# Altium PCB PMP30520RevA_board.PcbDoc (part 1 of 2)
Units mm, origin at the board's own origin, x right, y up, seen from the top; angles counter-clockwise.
Board outline 53.34 x 64.26 mm, 2 copper layers (Top Layer, Bottom Layer), stack 1.575 mm thick; 53 components, 27 nets, 127 pads, 140 vias.
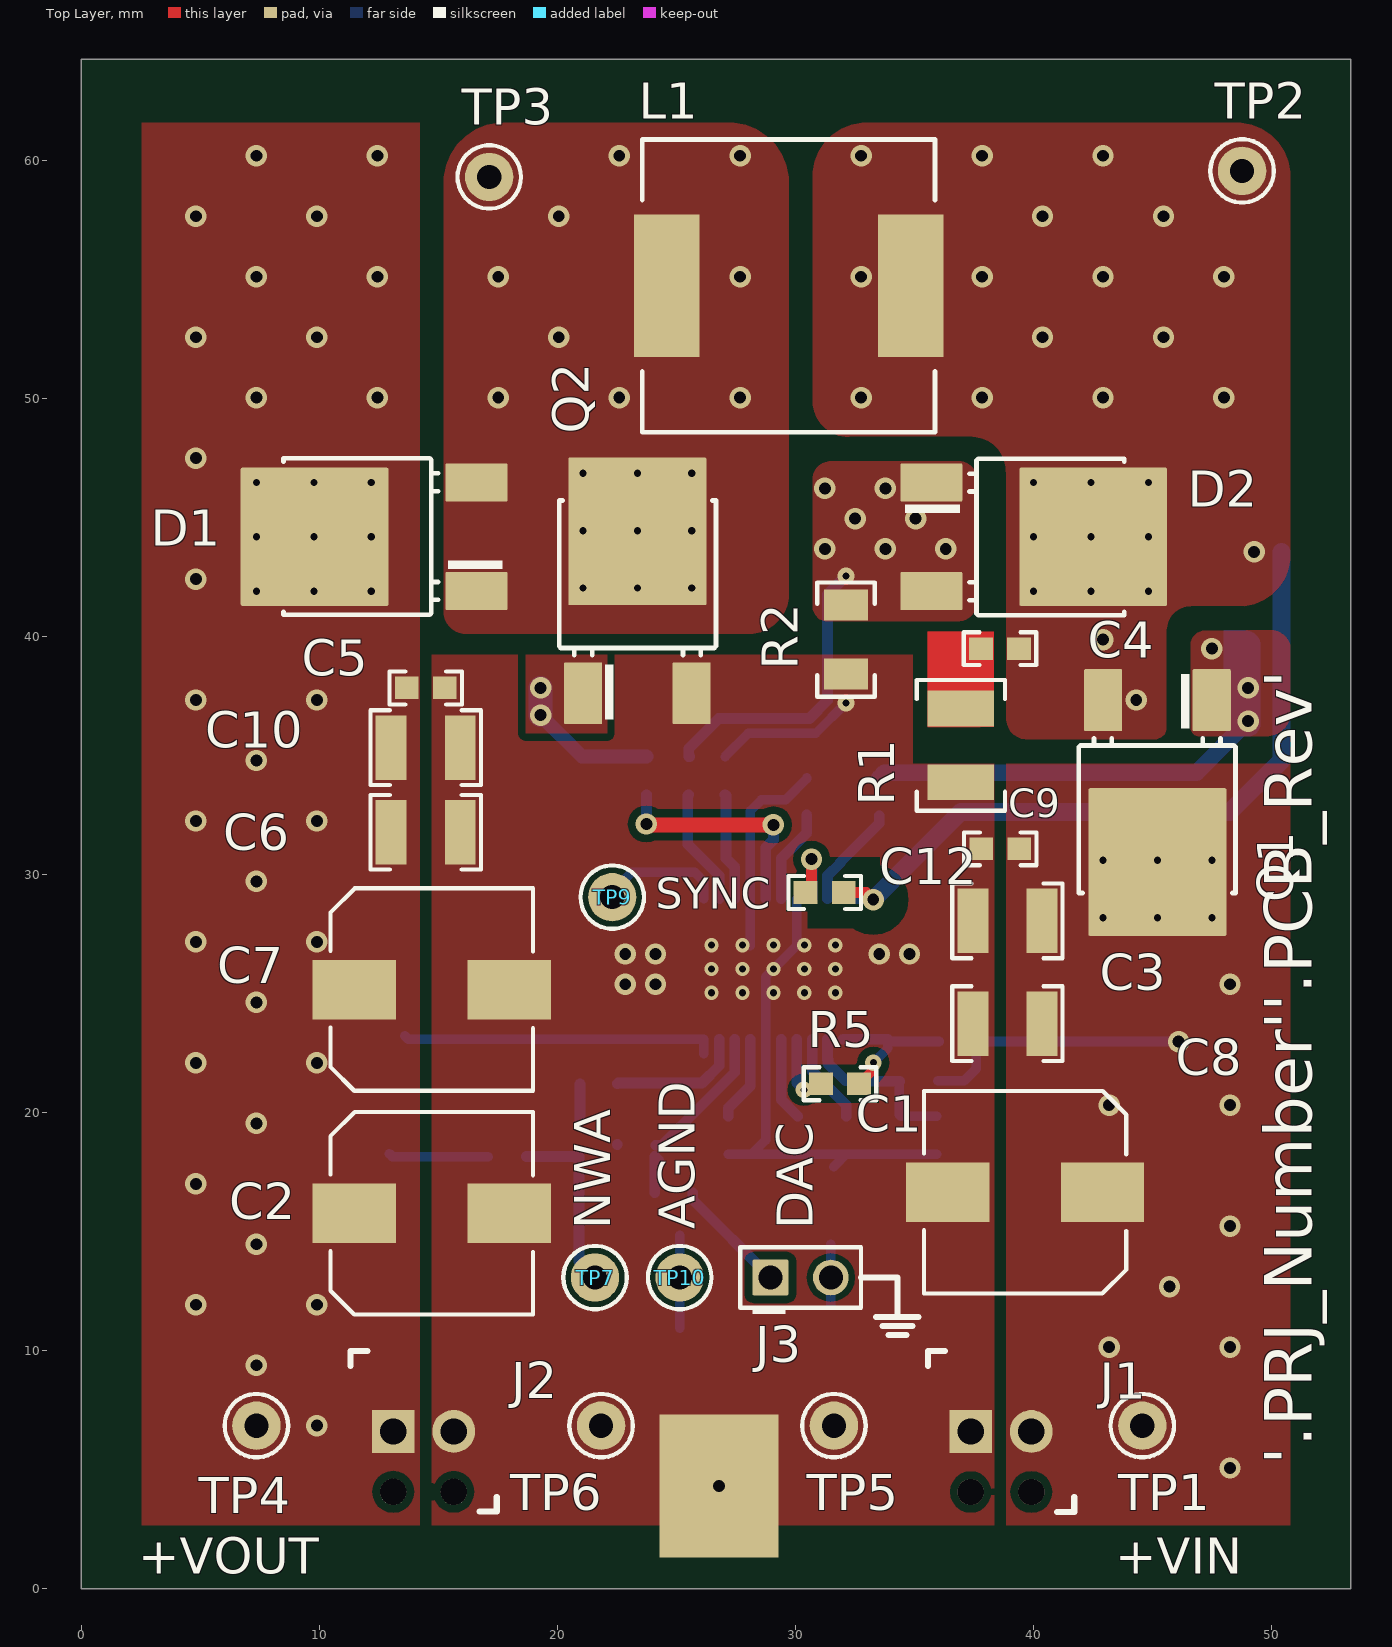
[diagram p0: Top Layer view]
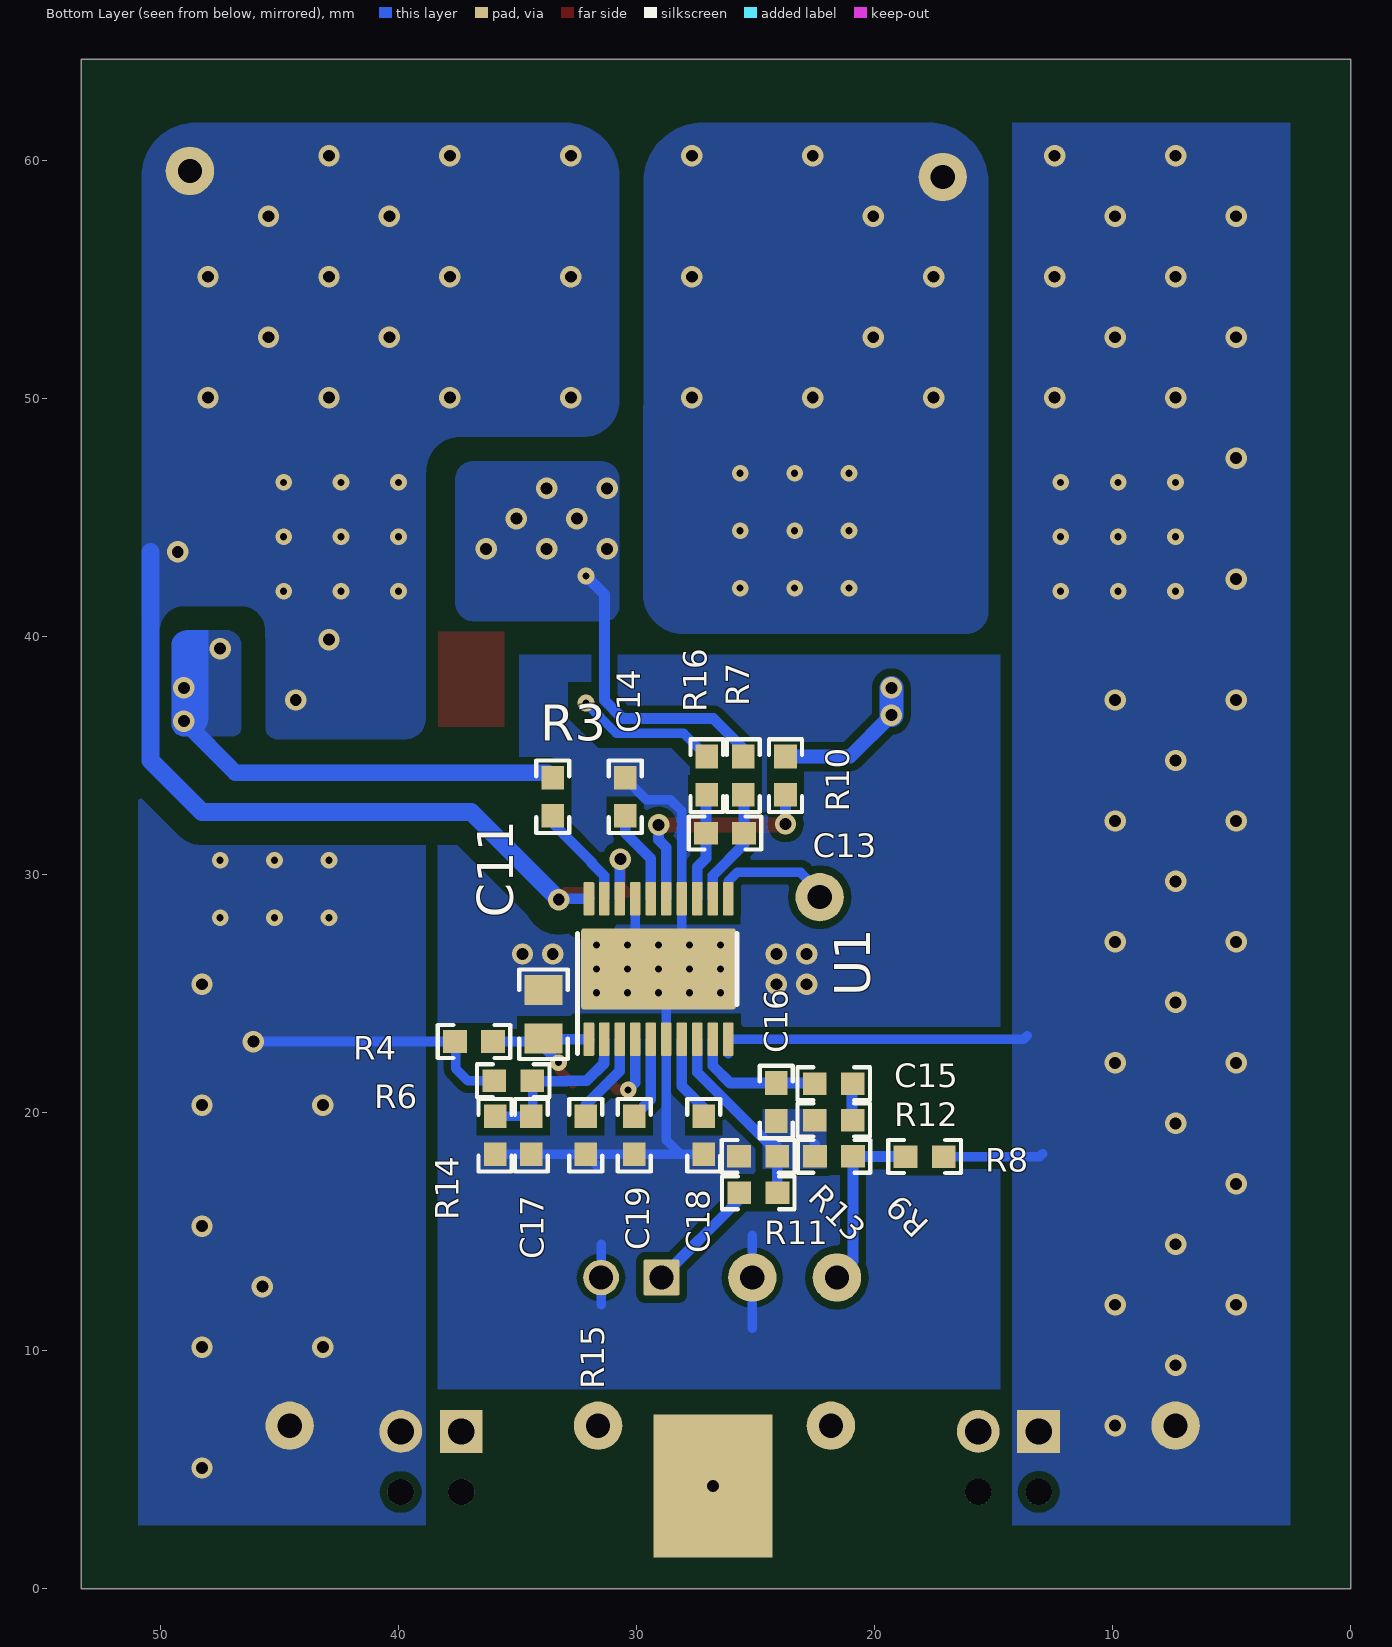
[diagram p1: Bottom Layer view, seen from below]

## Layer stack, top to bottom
Top Solder: solder mask 0.0102, Solder Resist, Dk 3.5
Top Layer: signal copper 0.0356
Dielectric1: core 1.5037, FR-4, Dk 4.8
Bottom Layer: signal copper 0.0356
Bottom Solder: solder mask 0.0102, Solder Resist, Dk 3.5

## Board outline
0,0 53.34,0 53.34,64.262 0,64.262

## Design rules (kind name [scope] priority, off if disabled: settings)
AcuteAngle [All] p1: minimum=4.50000000000000E+0001 checktracksonly=FALSE
AssemblyTestPointUsage [All] p1: valid=2
BoardOutlineClearance BoardOutlineClearance_MountingHoles [OnCopper and InComponentClass('Mounting Holes')] p1: gap=1.016 ignorepadtopadclearanceinfootprint=FALSE
BoardOutlineClearance BoardOutlineClearance_Poly [OnCopper and IsPoly] p2: gap=0.635 ignorepadtopadclearanceinfootprint=FALSE
BoardOutlineClearance [OnCopper and Not InComponentClass('Logo') and not InComponentClass('FiducialMark') and not InRegion(1000,500,4000,800) and not InPoly] p3: gap=1.905 ignorepadtopadclearanceinfootprint=FALSE
Clearance Clearance_Keepouts [((IsTrack Or IsArc) And Not InPoly) And IsFree and IsKeepOut vs ((IsTrack Or IsArc) And Not InPoly) And IsFree and IsKeepOut] p1: gap=0 ignorepadtopadclearanceinfootprint=FALSE
Clearance Clearance_sw1 [InPolygon vs InNet('NetC4_1')] p2: gap=1.016 ignorepadtopadclearanceinfootprint=TRUE except(0: Arc-Hole Track-Hole SMDPad-Hole THPad-Hole Via-Hole Fill-Hole Poly-Hole Region-Hole Text-Hole)
Clearance Clearance_Poly [InPolygon] p3: gap=0.32 ignorepadtopadclearanceinfootprint=FALSE except(0: Arc-Hole Track-Hole SMDPad-Hole THPad-Hole Via-Hole Fill-Hole Poly-Hole Region-Hole Text-Hole)
Clearance Clearance_FiducialMark [IsKeepOut and InComponentClass('FiducialMark') vs IsPad and InComponentClass('FiducialMark')] p4: gap=0 ignorepadtopadclearanceinfootprint=FALSE
Clearance [All] p5: gap=0.2 ignorepadtopadclearanceinfootprint=FALSE except(0: Arc-Hole Track-Hole SMDPad-Hole THPad-Hole Via-Hole Fill-Hole Poly-Hole Region-Hole Text-Hole)
ComponentClearance ComponentClearance_MountingHoles_FiducialMarks [InComponentClass('Mounting Holes') vs InComponentClass('FiducialMark')] p1: gap=1.27 collisioncheckmode=3 verticalgap=0.254 showdistances=FALSE
ComponentClearance ComponentClearance_Shunt [InComponentClass('Header') vs InComponentClass('Shunt')] p2: gap=0 collisioncheckmode=3 verticalgap=0 showdistances=FALSE
ComponentClearance ComponentClearance_Logo [InComponentClass('Logo')] p3: gap=1.27 collisioncheckmode=3 verticalgap=0.254 showdistances=FALSE
ComponentClearance ComponentClearance_ScrewToNut [(HasFootprint('NY PMS 440 0025 PH')) vs (HasFootprint('Keystone_1902C'))] p4: gap=0.127 collisioncheckmode=3 verticalgap=0.254 showdistances=FALSE
ComponentClearance ComponentClearance_MountingHoles [InComponentClass('Mounting Holes')] p5: gap=6.35 collisioncheckmode=3 verticalgap=2540 showdistances=FALSE
ComponentClearance ComponentClearance_SmallPassives [HasFootprint('0201*') or HasFootprint('0402*') or HasFootprint('0508') or HasFootprint('0603*') or HasFootprint('0612') or HasFootprint('0805*') or HasFootprint('0815*') or HasFootprint('0830*') or HasFootprint('1206*') or HasFootprint('1210*') or HasFootprint('1808*') or HasFootprint('1812*') or HasFootprint('1825*') or HasFootprint('2010*') or HasFootprint('2220*') or HasFootprint('2225*') or HasFootprint('2512*') or HasFootprint('2728*') or HasFootprint('3518*') vs HasFootprint('0201*') or HasFootprint('0402*') or HasFootprint('0508') or HasFootprint('0603*') or HasFootprint('0612') or HasFootprint('0805*') or HasFootprint('0815*') or HasFootprint('0830*') or HasFootprint('1206*') or HasFootprint('1210*') or HasFootprint('1808*') or HasFootprint('1812*') or HasFootprint('1825*') or HasFootprint('2010*') or HasFootprint('2220*') or HasFootprint('2225*') or HasFootprint('2512*') or HasFootprint('2728*') or HasFootprint('3518*')] p6: gap=0.38 collisioncheckmode=3 verticalgap=0.254 showdistances=FALSE
ComponentClearance ComponentClearance_THtoSMT [IsThruComponent vs IsSMTComponent] p7: gap=1.016 collisioncheckmode=3 verticalgap=0.762 showdistances=FALSE
ComponentClearance ComponentClearance_THtoTH [IsThruComponent vs IsThruComponent] p8: gap=0.762 collisioncheckmode=3 verticalgap=0.762 showdistances=FALSE
ComponentClearance [All] p9: gap=0.762 collisioncheckmode=3 verticalgap=0.254 showdistances=FALSE
DiffPairsRouting [All] p1: maxlimit=2.54 minlimit=0.254 mostfreqgap=0.254 toplayer_minwidth=0.381 toplayer_maxwidth=0.381 toplayer_prefwidth=0.381 bottomlayer_minwidth=0.381 bottomlayer_maxwidth=0.381 bottomlayer_prefwidth=0.381 maxuncoupledlength=25.4
FabricationTestPointUsage TestPointUsage [All] p1: valid=2 allowmultiple=FALSE
FabricationTestpoint Testpoint [All] p1: side=3 testpointundercomponent=TRUE minsize=1.016 maxsize=2.54 preferedsize=1.524 minholesize=0 maxholesize=1.016 preferedholesize=0.813 testpointgrid=0.025 allowsidetop=TRUE allowsidebottom=TRUE usegrid=TRUE gridtolerance=0
FanoutControl Fanout_LCC [IsLCC] p1: bgadir=Out bgaviamode=Centered fanoutstyle=Auto fanoutdirection=Alternating viagrid=0.025 // Fanout_LCC (Default Rule)
FanoutControl Fanout_BGA [IsBGA] p2: bgadir=Out bgaviamode=Centered fanoutstyle=Auto fanoutdirection=Alternating viagrid=0.025 // Fanout_BGA (Default Rule)
FanoutControl Fanout_Default [All] p4: bgadir=Out bgaviamode=Centered fanoutstyle=Auto fanoutdirection=Alternating viagrid=0.025 // Fanout_Default (Default Rule)
FanoutControl Fanout_Small [(CompPinCount < 5)] p5: bgadir=Out bgaviamode=Centered fanoutstyle=Auto fanoutdirection=OutThenIn viagrid=0.025 // Fanout_Small (Default Rule)
HoleSize [All] p1: absolutevalues=TRUE maxlimit=6.375 minlimit=0.3 maxpercent=80.000 minpercent=20.000
MinimumAnnularRing MinimumAnnularRing_ThermalPadVias [IsVia and InAnyComponent] p1: minimumring=0.15
MinimumAnnularRing [All] p2: minimumring=0.2
MinimumSolderMaskSliver MinimumSolderMaskSliver_Logo [InComponentClass('Logo') vs InComponentClass('Logo')] p1: minsoldermaskwidth=0.018
MinimumSolderMaskSliver [All] p2: minsoldermaskwidth=0.1
PlaneConnect [All] p1: planeconnectstyle=Relief reliefexpansion=0.254 reliefentries=4 reliefconductorwidth=0.254 reliefairgap=0.254
PolygonConnect PolygonConnect_J3 [All vs InComponent('J3')] p1: connectstyle=NoConnect reliefconductorwidth=0.254 reliefentries=4 polygonreliefangle="90 Angle" airgapwidth=0.254
PolygonConnect PolygonConnect_TP10 [All vs (InComponent('TP10'))] p2: connectstyle=NoConnect reliefconductorwidth=0.254 reliefentries=4 polygonreliefangle="90 Angle" airgapwidth=0.254
PolygonConnect PolygonConnect_r16 [All vs (InComponent('R16'))] p3: connectstyle=NoConnect reliefconductorwidth=0.254 reliefentries=4 polygonreliefangle="90 Angle" airgapwidth=0.254
PolygonConnect [All] p4: connectstyle=Direct reliefconductorwidth=0.254 reliefentries=4 polygonreliefangle="90 Angle" airgapwidth=0.254
RoutingVias ThermalPadVias [IsVia and InAnyComponent] p1: holewidth=0.3 width=0.7 viastyle="Through Hole" minholewidth=0.3 minwidth=0.6 maxholewidth=0.6 maxwidth=1.6
RoutingVias [All] p2: holewidth=0.3 width=0.7 viastyle="Through Hole" minholewidth=0.3 minwidth=0.6 maxholewidth=1.016 maxwidth=2
SilkToBoardRegionClearance [Not ((IsComment or IsDesignator) And (Hide <> 'False')) and not InRegion(1000,500,4000,800)] p1:
SilkToSilkClearance SilkToSilkClearance_Pb-FreeLogo [(HasFootprint('Pb-Free_Overlay_Medium') OR HasFootprint('Pb-Free_Overlay_Small')) vs (HasFootprint('Pb-Free_Overlay_Medium') OR HasFootprint('Pb-Free_Overlay_Small'))] p1: silktosilkclearance=0
SilkToSilkClearance [All] p2: silktosilkclearance=0.102
SilkToSolderMaskClearance SilkToComponentPadClearance [(IsPad or IsFill or IsRegion) and InAnycomponent] p1: minsilkscreentomaskgap=0.127 clearancetoexposedcopper=TRUE
SilkToSolderMaskClearance "Silk to Solder Mask Opening" [All] p2: minsilkscreentomaskgap=0.102 clearancetoexposedcopper=FALSE
SolderMaskExpansion [All] p1: expansion=0.05
Width [All] p1: maxlimit=2.54 minlimit=0.152 preferedwidth=0.254 checkconnectedcopper=TRUE
15 further rules are at their usual default settings.

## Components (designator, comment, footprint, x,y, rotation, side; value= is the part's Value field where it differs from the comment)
C1 "EEHZC1V151P" SM_RADIAL_8MM 39.657,16.661 r180 top value=150uF
C2 "EEHZC1V151P" SM_RADIAL_8MM 14.732,15.781 r0 top value=150uF
C3 "GRM32ER71H106KA12L" 1210_270 38.91,28.062 r180 top value=10uF
C4 "GRM188R71H471KA01D" 0603 38.6,39.497 r180 top value=470pF
C5 "GCM188R71H104KA57D" 0603 14.478,37.846 r0 top value=0.1uF
C6 "GRM32ER71H106KA12L" 1210_270 14.478,31.783 r0 top value=10uF
C7 "EEHZC1V151P" SM_RADIAL_8MM 14.732,25.179 r0 top value=150uF
C8 "GRM32ER71H106KA12L" 1210_270 38.91,23.744 r180 top value=10uF
C9 "GCM188R71H104KA57D" 0603 38.608,31.086 r180 top value=0.1uF
C10 "GRM32ER71H106KA12L" 1210_270 14.478,35.339 r0 top value=10uF
C11 "GRM21BR71H105KA12L" 0805_HV 33.917,24.138 r90 bottom value=1uF
C12 "GCM188R71H104KA57D" 0603 31.235,29.253 r180 top value=0.1uF
C13 "GRM1885C1H101JA01D" 0603 26.289,31.75 r180 bottom value=100pF
C14 "GRM188Z71C475KE21D" 0603 30.48,33.274 r90 bottom value=4.7uF
C15 "GRM188R71E104KA01D" 0603 21.725,21.217 r180 bottom value=0.1uF
C16 "GRM188R71H391KA01D" 0603 24.138,20.455 r270 bottom value=390pF
C17 "GRM188R71E104KA01D" 0603 34.425,19.058 r270 bottom value=0.1uF
C18 "GRM188R71E104KA01D" 0603 27.186,19.058 r270 bottom value=0.1uF
C19 "GRM188R71H221KA01D" 0603 30.107,19.058 r270 bottom value=220pF
D1 "VS-50WQ04FNTRHM3" DPAK 13.208,44.196 r180 top value=40V
D2 "VS-50WQ04FNTRHM3" DPAK 39.116,44.196 r0 top value=40V
J1 "1725656" CONN_1725656 38.643,6.615 r0 top
J2 "1725656" CONN_1725656 14.386,6.619 r0 top
J3 "DAC" CONN_PEC02SAAN 30.226,13.081 r0 top
L1 "931BS-100M" D128C 29.718,54.737 r180 top value=10uH
Q1 "IPD50N04S4-10" DPAK 45.212,33.933 r270 top value=40V
Q2 "IPD50N04S4-10" DPAK 23.368,41.021 r90 top value=40V
R1 "CRCW121010R0FKEAHP" 1210M 36.957,35.433 r270 top value=10.0
R2 "CSR1206FK25L0" 1206 32.131,39.878 r270 top value=0.025
R3 "CRCW060310R0FKEA" 0603 33.528,33.274 r90 bottom value=10.0
R4 "CRCW060310R0FKEA" 0603 36.838,22.995 r0 bottom value=10.0
R5 "CRCW06031M00FKEA" 0603 31.877,21.217 r0 top value=1.00Meg
R6 "CRCW0603100KFKEA" 0603 35.187,21.344 r0 bottom value=100k
R7 "CRCW0603100RFKEA" 0603 25.527,34.163 r90 bottom value=100
R8 "CRCW060349R9FKEA" 0603 17.907,18.161 r180 bottom value=49.9
R9 "CRCW060310K0FKEA" 0603 21.717,18.169 r180 bottom value=10.0k
R10 "CRCW060310R0FKEA" 0603 23.749,34.163 r270 bottom value=10.0
R11 "CRCW06032K55FKEA" 0603 24.892,16.637 r0 bottom value=2.55k
R12 "CRCW060310K0FKEA" 0603 21.725,19.693 r180 bottom value=10.0k
R13 "CRCW06031K02FKEA" 0603 24.9,18.169 r180 bottom value=1.02k
R14 "CRCW060315K8FKEA" 0603 35.949,19.058 r90 bottom value=15.8k
R15 "CRCW060315K4FKEA" 0603 32.139,19.058 r90 bottom value=15.4k
R16 "CRCW0603100RFKEA" 0603 27.051,34.163 r90 bottom value=100
TP1 "5000" Keystone5000 44.577,6.858 r0 top value=Red
TP2 "5002" Keystone5002 48.768,59.563 r90 top
TP3 "5002" Keystone5002 17.145,59.309 r90 top
TP4 "5000" Keystone5000 7.366,6.858 r90 top value=Red
TP5 "5001" Keystone5001 31.623,6.858 r90 top value=Black
TP6 "5001" Keystone5001 21.844,6.858 r90 top value=Black
TP7 "NWA" Keystone5003 21.59,13.081 r90 top
TP9 "SYNC" Keystone5002 22.313,29.059 r90 top
TP10 "AGND" Keystone5001 25.146,13.081 r90 top value=Black
U1 "LM25118Q1MHX/NOPB" PWP0020A_N 29.083,26.043 r90 bottom

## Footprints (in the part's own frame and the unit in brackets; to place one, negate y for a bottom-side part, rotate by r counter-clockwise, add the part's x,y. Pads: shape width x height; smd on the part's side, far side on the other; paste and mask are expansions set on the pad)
0603 [mm] "0603 from SM-752 data"
  rect 1x0.95 smd: 1(-0.8,0) 2(0.8,0)
  silkscreen extent -1.52,-0.69 1.52,0.69, body extent -0.87,-0.47 0.87,0.47, height 1
0805_HV [mil] "0805 with 30mil clearance between pads"
  rect 50x63 smd: 1(-40,0) 2(40,0)
  silkscreen extent -74,-40 74,40, body extent -43,-29 43,29, height 57
1206 [mm] "1206 from SM-752 data"
  rect 1.3x1.85 smd: 1(-1.45,0) 2(1.45,0)
  silkscreen extent -2.4,-1.21 2.4,1.21, body extent -1.7,-0.9 1.7,0.9, height 1.35
1210_270 [mm] "1210"
  rect 1.3x2.7 smd: 1(-1.45,0) 2(1.45,0)
  silkscreen extent -2.32,-1.57 2.32,1.57, body extent -1.7,-1.35 1.7,1.35, height 2.7
1210M [mm] "1210 from SM-752 data"
  rect 1.5x2.8 smd: 1(-1.55,0) 2(1.55,0)
  silkscreen extent -2.75,-1.85 2.75,1.85, body extent -1.7,-1.35 1.7,1.35, height 1.35
CONN_1725656 [mm] "Phoenix Contact"
  rect 1.8x1.8 hole 1.1: 1(-1.27,0)
  round 1.8 hole 1.1: 2(1.27,0)
  round 1.1 hole 1.1 unplated: MH1(-1.275,-2.54) MH2(1.27,-2.54)
  silkscreen extent -3.08,-3.37 3.08,3.37, body extent -2.77,-3.1 2.77,3.1, height 8.52
CONN_PEC02SAAN [mm] "SULLINS"
  rrect7% 1.5x1.5 hole 1.016: 1(-1.27,0)
  round 1.5 hole 1.016: 2(1.27,0)
  silkscreen extent -2.54,-1.52 2.54,1.27, body extent -2.54,-1.27 2.54,1.27, height 8.38
D128C [mm] "TOKO"
  rect 2.75x6 smd: 1(-5.125,0) 2(5.125,0)
  silkscreen extent -6.15,-6.15 6.15,6.15, body extent -6.15,-6.15 6.15,6.15, height 8
DPAK [mm] "D-PAK, 3-Pads, Body 6.22x6.73mm (max), TO-252AA using nominal STEP model"
  rrect6% 2.6x1.6 smd: 1(-3.4,2.28) 3(-3.4,-2.28)
  rrect2% 6.2x5.8 smd paste-2.9: 4(3.4,0)
  silkscreen extent -4.5,-3.3 4.7,3.28, body extent -3.86,-3.29 5.84,3.29, height 2.48
Keystone5000 [mil] "For Keystone 500x miniature loop terminals"
  round 80 hole 40: 1(0,0)
  silkscreen extent -52,-52 52,52, body extent -49,-49 49,49, height 182
Keystone5001 [mil] "For Keystone 500x miniature loop terminals"
  round 80 hole 40: 1(0,0)
  silkscreen extent -52,-52 52,52, body extent -49,-49 49,49, height 182
Keystone5002 [mil] "For Keystone 500x miniature loop terminals"
  round 80 hole 40: 1(0,0)
  silkscreen extent -52,-52 52,52, body extent -49,-49 49,49, height 182
Keystone5003 [mil] "For Keystone 500x miniature loop terminals"
  round 80 hole 40: 1(0,0)
  silkscreen extent -52,-52 52,52, body extent -49,-49 49,49, height 182
PWP0020A_N [mm] "TSOP, 20-Leads, Body 6.5x4.4mm, Pitch 0.65mm, Exposed Pad, IPC Medium Density"
  rrect22% 1.4x0.45 smd: 1(-2.95,2.925) 2(-2.95,2.275) 3(-2.95,1.625) 4(-2.95,0.975) 5(-2.95,0.325) 6(-2.95,-0.325) 7(-2.95,-0.975) 8(-2.95,-1.625) 9(-2.95,-2.275) 10(-2.95,-2.925) 11(2.95,-2.925) 12(2.95,-2.275) 13(2.95,-1.625) 14(2.95,-0.975) 15(2.95,-0.325) 16(2.95,0.325) 17(2.95,0.975) 18(2.95,1.625) 19(2.95,2.275) 20(2.95,2.925)
  rrect6% 3.4x6.5 smd paste-2 mask-2: 21(0,0)
  rrect3% 3.15x4.35 on Bottom Paste: 21(0,0)
  rrect3% 3.15x4.35 on Bottom Solder: 21(0,0)
  silkscreen extent -3.55,-3.3 1.5,3.4, body extent -3.21,-3.25 3.21,3.25, height 1
SM_RADIAL_8MM [mm] "Nichicon 8x10"
  rect 3.5x2.5 smd: 1(-3.25,0) 2(3.25,0)
  silkscreen extent -4.25,-4.25 4.25,4.25, body extent -4.25,-4.25 4.25,4.25, height 10.5

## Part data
C1 C2 C7: "CAP, Polymer Hybrid, 150 µF, 35 V,+/- 20%, 27 ohm, 8x10 SMD", Manufacturer=Panasonic, Supplier Part Number 1=P15470CT-ND, Tolerance_%=20, Value1="27 ohm", Value2=35V, ValueDisplayed=150µF
C3 C6 C8 C10: "CAP, CERM, 10 µF, 50 V,+/- 10%, X7R, 1210", Cap_Case=1210, Manufacturer=MuRata, Supplier Part Number 1=490-6544-1-ND, TempCo=X7R, Tolerance_%=10, Value2=50V, ValueDisplayed=10µF
C4: "CAP, CERM, 470 pF, 50 V,+/- 10%, X7R, 0603", Cap_Case=0603, Manufacturer=MuRata, Supplier Part Number 1=490-1489-1-ND, TempCo=X7R, Tolerance_%=10, Value2=50V, ValueDisplayed=470pF
C5 C9 C12: "CAP, CERM, 0.1 µF, 50 V,+/- 10%, X7R, 0603", Cap_Case=0603, Manufacturer=MuRata, Supplier Part Number 1=490-4779-1-ND, TempCo=X7R, Tolerance_%=10, Value1="0.02 ohm", Value2=50V, ValueDisplayed=0.1µF
C11: "CAP, CERM, 1 µF, 50 V,+/- 10%, X7R, 0805", Cap_Case=0805, Manufacturer=MuRata, Supplier Part Number 1=490-4736-1-ND, TempCo=X7R, Tolerance_%=10, Value2=50V, ValueDisplayed=1µF
C13: "CAP, CERM, 100 pF, 50 V,+/- 5%, C0G/NP0, 0603", Cap_Case=0603, Manufacturer=MuRata, Supplier Part Number 1=490-1427-1-ND, TempCo=C0G/NP0, Tolerance_%=5, Value2=50V, ValueDisplayed=100pF
C14: "CAP, CERM, 4.7 µF, 16 V,+/- 10%, X7R, 0603", Cap_Case=0603, Manufacturer=MuRata, TempCo=X7R, Tolerance_%=10, Value2=16V, ValueDisplayed=4.7µF
C15 C17 C18: "CAP, CERM, 0.1 µF, 25 V,+/- 10%, X7R, 0603", Cap_Case=0603, Manufacturer=MuRata, Supplier Part Number 1=490-1524-1-ND, TempCo=X7R, Tolerance_%=10, Value2=25V, ValueDisplayed=0.1µF
C16: "CAP, CERM, 390 pF, 50 V,+/- 10%, X7R, 0603", Cap_Case=0603, Manufacturer=MuRata, Supplier Part Number 1=490-1555-1-ND, TempCo=X7R, Tolerance_%=10, Value2=50V, ValueDisplayed=390pF
C19: "CAP, CERM, 220 pF, 50 V,+/- 10%, X7R, 0603", Cap_Case=0603, Manufacturer=MuRata, Supplier Part Number 1=490-1483-1-ND, TempCo=X7R, Tolerance_%=10, Value2=50V, ValueDisplayed=220pF
D1 D2: "Diode, Schottky, 40 V, 5.5 A, AEC-Q101, DPAK", Manufacturer=Vishay-Semiconductor, Supplier Part Number 1=VS-50WQ04FNTRHM3-ND, Value1=5.5A, Value2=0.51V
J1 J2: "Terminal Block, 100mil, 2x1, 6A, 63V, TH", Manufacturer="Phoenix Contact", Supplier Part Number 1=651-1725656
J3: library part PEC02SAAN, "Header, 100mil, 2x1, Tin, TH", Color=Black, Current_A=3, Manufacturer="Sullins Connector Solutions", Supplier Part Number 1=S1012E-02-ND, Voltage_V=1800
L1: "Inductor, Shielded, Ferrite, 10 µH, 7.8 A, 0.011 ohm, SMD", Manufacturer="MuRata Toko", Value1="0.011 ohm", Value2=7.8A, ValueDisplayed=10µH
Q1 Q2: library part IPD90N04S304ATMA1, "MOSFET, N-CH, 40 V, 50 A, AEC-Q101, DPAK", Alternate Manufacturer=None, Manufacturer="Infineon Technologies", Value1="? ohm", Value2="14 nC"
R1: "RES, 10.0, 1%, 0.75 W, AEC-Q200 Grade 0, 1210", Manufacturer=Vishay-Dale, Power_W=0.75, Supplier Part Number 1=541-10.0DCT-ND, TempCo="100 ppm/C", Tolerance_%=1, Value1=1%, Value2=0.75W, Value_Code=10R0, ValueDisplayed=10.0
R2: "RES, 0.025, 1%, 0.5 W, 1206", Manufacturer="Stackpole Electronics Inc", Power_W=0.5, Supplier Part Number 1=CSR1206FK25L0CT-ND, TempCo="100 ppm/C", Tolerance_%=1, Value1=1%, Value2=0.5W, Value_Code=R025, ValueDisplayed=0.025
R3 R4 R10: "RES, 10.0, 1%, 0.1 W, 0603", Manufacturer=Vishay-Dale, Power_W=0.1, Supplier Part Number 1=541-10.0HCT-ND, TempCo="100 ppm/C", Tolerance_%=1, Value1=1%, Value2=0.1W, Value_Code=10R0, ValueDisplayed=10.0
R5: "RES, 1.00 M, 1%, 0.1 W, 0603", Manufacturer=Vishay-Dale, Power_W=0.1, Supplier Part Number 1=541-1.00MHCT-ND, TempCo="100 ppm/C", Tolerance_%=1, Value1=1%, Value2=0.1W, Value_Code=1M00, ValueDisplayed=1.00M
R6: "RES, 100 k, 1%, 0.1 W, 0603", Manufacturer=Vishay-Dale, Power_W=0.1, Supplier Part Number 1=541-100KHCT-ND, TempCo="100 ppm/C", Tolerance_%=1, Value1=1%, Value2=0.1W, Value_Code=100k
R7 R16: "RES, 100, 1%, 0.1 W, 0603", Manufacturer=Vishay-Dale, Power_W=0.1, Supplier Part Number 1=541-100HCT-ND, TempCo="100 ppm/C", Tolerance_%=1, Value1=1%, Value2=0.1W, Value_Code=100R, ValueDisplayed=100
R8: "RES, 49.9, 1%, 0.1 W, 0603", Manufacturer=Vishay-Dale, Power_W=0.1, Supplier Part Number 1=541-49.9HCT-ND, TempCo="100 ppm/C", Tolerance_%=1, Value1=1%, Value2=0.1W, Value_Code=49R9, ValueDisplayed=49.9
R9 R12: "RES, 10.0 k, 1%, 0.1 W, 0603", Manufacturer=Vishay-Dale, Power_W=0.1, Supplier Part Number 1=541-10.0KHCT-ND, TempCo="100 ppm/C", Tolerance_%=1, Value1=1%, Value2=0.1W, Value_Code=10k0, ValueDisplayed=10.0k
R11: "RES, 2.55 k, 1%, 0.1 W, 0603", Manufacturer=Vishay-Dale, Power_W=0.1, Supplier Part Number 1=541-2.55KHCT-ND, TempCo="100 ppm/C", Tolerance_%=1, Value1=1%, Value2=0.1W, Value_Code=2k55, ValueDisplayed=2.55k
R13: "RES, 1.02 k, 1%, 0.1 W, 0603", Manufacturer=Vishay-Dale, Power_W=0.1, Supplier Part Number 1=541-1.02KHCT-ND, TempCo="100 ppm/C", Tolerance_%=1, Value1=1%, Value2=0.1W, Value_Code=1k02, ValueDisplayed=1.02k
R14: "RES, 15.8 k, 1%, 0.1 W, 0603", Manufacturer=Vishay-Dale, Power_W=0.1, Supplier Part Number 1=541-15.8KHCT-ND, TempCo="100 ppm/C", Tolerance_%=1, Value1=1%, Value2=0.1W, Value_Code=15k8, ValueDisplayed=15.8k
R15: "RES, 15.4 k, 1%, 0.1 W, 0603", Manufacturer=Vishay-Dale, Power_W=0.1, Supplier Part Number 1=541-15.4KHCT-ND, TempCo="100 ppm/C", Tolerance_%=1, Value1=1%, Value2=0.1W, Value_Code=15k4, ValueDisplayed=15.4k
TP1 TP4: "Test Point, Miniature, Red, TH", Manufacturer=Keystone, Supplier Part Number 1=5000K-ND
TP2 TP3: "Test Point, Miniature, White, TH", Color=White, Manufacturer=Keystone, Supplier Part Number 1=36-5002-ND
TP5 TP6: "Test Point, Miniature, Black, TH", Manufacturer=Keystone, Supplier Part Number 1=5001K-ND
TP7: library part 5003, "Test Point, Miniature, Orange, TH", Color=Orange, Manufacturer=Keystone, Supplier Part Number 1=36-5003-ND
TP9: library part 5002, "Test Point, Miniature, White, TH", Color=White, Manufacturer=Keystone, Supplier Part Number 1=36-5002-ND
TP10: library part 5001, "Test Point, Miniature, Black, TH", Manufacturer=Keystone, Supplier Part Number 1=5001K-ND
U1: "Automotive Grade, 3-42V Wide Vin, Current Mode Non-Synchronous Buck-Boost Controller, PWP0020A (TSSOP-20)", Alternate Manufacturer="Texas Instruments", Alternate PartNumber=LM25118Q1MH/NOPB

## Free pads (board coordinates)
  rect 5x6 hole 0.5: 1(26.797,4.318)

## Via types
v1: diameter 0.9, hole 0.5, Top Layer to Bottom Layer, 60 vias
v2: diameter 0.7, hole 0.3, Top Layer to Bottom Layer, 34 vias
v3: diameter 0.9, hole 0.5, Top Layer to Bottom Layer, tented top, 25 vias
v4: diameter 0.6, hole 0.3, Top Layer to Bottom Layer, 9 vias
v5: diameter 0.6, hole 0.3, Top Layer to Bottom Layer, tented both sides, 6 vias
v6: diameter 0.9, hole 0.5, Top Layer to Bottom Layer, tented bottom, 2 vias
v7: diameter 0.7, hole 0.3, Top Layer to Bottom Layer, tented both sides, 2 vias
v8: diameter 0.7, hole 0.3, Top Layer to Bottom Layer, tented bottom, 1 vias
v9: diameter 0.9, hole 0.5, Top Layer to Bottom Layer, tented both sides, 1 vias

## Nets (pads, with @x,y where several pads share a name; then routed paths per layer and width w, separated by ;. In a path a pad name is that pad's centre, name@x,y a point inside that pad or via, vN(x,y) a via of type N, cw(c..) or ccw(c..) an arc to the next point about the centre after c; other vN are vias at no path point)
GND: C1.2 C2.2 C3.2 C5.2 C6.2 C7.2 C8.2 C9.2 C10.2 C11.2 C14.2 C17.2 C18.2 C19.2 J1.1 J2.2 J3.2 pad.1 Q2.3 R1.2 R2.2 R13.1 R14.1 R15.1 R16.2 TP5.1 TP6.1 TP10.1 U1.6 U1.14 U1.17 U1.21@29.083,26.043 | length 42.1
  Bottom Layer w0.4: 25.146,14.859 25.149,10.946 ; R16.2@27.051,34.963 28.029,35.941 30.861,35.941 v8(32.131,37.211) ; C18.2@27.186,18.258 28.164,18.258 ; U1.21@28.108,27.018 U1.14@28.108,28.993 28.108,32.68 28.575,33.147 29.591,33.147 30.48,34.036 C14.2@30.48,34.074 ; U1.17@30.058,28.993 30.058,27.018 v4(29.083,26.043) 28.758,25.718 U1.6@28.758,23.093 28.758,18.852 28.164,18.258 ; 31.496,11.938 31.496,14.478 ; 31.623,17.742 R15.1@32.139,18.258 ; R14.1@35.949,18.258 C17.2@34.425,18.258 R15.1@32.139,18.258 ; 28.164,18.258 C19.2@30.107,18.258 R15.1@32.139,18.258
  other v1: 22.86,25.4 22.86,26.67 24.13,26.67 33.528,26.67 34.798,26.67
  other v4: 27.783,25.043 29.083,25.043 30.383,25.043 27.783,26.043 30.383,26.043 27.783,27.043 29.083,27.043 30.383,27.043
  other v5: 26.483,25.043 31.683,25.043 26.483,26.043 31.683,26.043 26.483,27.043 31.683,27.043
  other v6: 24.13,25.4
NetC1_1: C1.1 C3.1 C8.1 C9.1 J1.2 Q1.4 R4.2 R6.2 TP1.1 | length 11.5
  Bottom Layer w0.4: R6.2@35.987,21.344 37.092,21.344 37.592,21.844 37.592,22.949 R4.2@37.638,22.995 46.101,22.995 v1(46.101,22.987)
  other v1: 48.26,5.08 43.18,10.16 48.26,10.16 45.72,12.7 48.26,15.24 48.26,20.32 48.26,25.4
  other v2: 42.926,28.194 45.212,28.194 47.498,28.194 42.926,30.607 45.212,30.607 47.498,30.607
  other v3: 43.18,20.32
NetC2_1: C2.1 C5.1 C6.1 C7.1 C10.1 D1.4 J2.1 R8.2 TP4.1 U1.10 | length 17.5
  Bottom Layer w0.4: 12.954,18.288 13.081,18.161 R8.2@17.107,18.161 ; 13.589,23.241 13.737,23.093 U1.10@26.158,23.093 U1.10@26.158,22.475
  other v1: 9.906,6.858 7.366,9.398 4.826,11.938 7.366,14.478 4.826,17.018 7.366,19.558 4.826,22.098 9.906,22.098 7.366,24.638 4.826,27.178 9.906,27.178 7.366,29.718 4.826,32.258 9.906,32.258 7.366,34.798 4.826,37.338 9.906,37.338 4.826,42.418 4.826,47.498 7.366,50.038 12.446,50.038 4.826,52.578 9.906,52.578 7.366,55.118 12.446,55.118 4.826,57.658 9.906,57.658 7.366,60.198 12.446,60.198
  other v2: 7.366,41.91 9.779,41.91 12.192,41.91 7.366,44.196 9.779,44.196 12.192,44.196 7.366,46.482 9.779,46.482 12.192,46.482
  other v3: 9.906,11.938
NetC4_1: C4.1 C12.1 D2.4 L1.1 Q1.3 TP2.1 U1.20 | length 31
  Top Layer w0.45: C12.1@32.035,29.253 32.977,29.253 v6(33.274,28.956)
  Bottom Layer w0.45: U1.20@32.008,28.993 33.237,28.993 v6(33.274,28.956)
  Bottom Layer w0.75: v6(33.274,28.956) 36.951,32.633 48.254,32.633 50.419,34.798 50.419,43.561
  other v1: 49.276,43.561 48.006,50.038 45.466,52.578 48.006,55.118 45.466,57.658
  other v2: 40.005,41.91 42.418,41.91 44.831,41.91 40.005,44.196 42.418,44.196 44.831,44.196 40.005,46.482 42.418,46.482 44.831,46.482
  other v3: 44.323,37.338 42.926,39.878 32.766,50.038 37.846,50.038 42.926,50.038 40.386,52.578 32.766,55.118 37.846,55.118 42.926,55.118 40.386,57.658 32.766,60.198 37.846,60.198 42.926,60.198
NetC4_2: C4.2 R1.1
NetC11_1: C11.1 R4.1 R5.2 U1.1 | length 6.4
  Top Layer w0.4: R5.2@32.677,21.217 33.282,21.822 v7(33.282,22.106)
  Bottom Layer w0.4: v7(33.282,22.106) 33.888,22.712 33.888,23.093 33.986,22.995 R4.1@36.038,22.995
  Bottom Layer w0.45: U1.1@32.008,23.093 C11.1@33.888,23.093
NetC12_2: C12.2 U1.18 | length 3.2
  Top Layer w0.45: C12.2@30.435,29.253 30.683,29.501 v9(30.683,30.658)
  Bottom Layer w0.45: U1.18@30.708,28.993 v9@30.708,30.708
NetC13_1: C13.1 R16.1 U1.13 | length 4.5
  Bottom Layer w0.45: R16.1@27.051,33.363 27.089,33.325 C13.1@27.089,31.75 27.089,30.696 27.458,30.327 U1.13@27.458,28.993
NetC13_2: C13.2 R7.1 U1.12 | length 4.9
  Bottom Layer w0.45: R7.1@25.527,33.363 25.489,33.325 C13.2@25.489,31.75 25.489,31.28 26.808,29.961 U1.12@26.808,28.993
NetC14_1: C14.1 U1.16 | length 4
  Bottom Layer w0.45: U1.16@29.408,28.993 29.408,30.678 30.48,31.75 C14.1@30.48,32.512
NetC15_1: C15.1 C16.1 U1.9 | length 5.7
  Bottom Layer w0.45: C15.1@22.525,21.217 22.563,21.255 C16.1@24.138,21.255 26.081,21.255 26.808,21.982 U1.9@26.808,23.093
NetC15_2: C15.2 R12.2 | length 1.5
  Bottom Layer w0.45: R12.2@20.955,19.685 C15.2@20.955,21.209
NetC16_2: C16.2 R9.1 R11.1 R12.1 R13.2 U1.8 | length 7.7
  Bottom Layer w0.45: 22.517,18.669 22.525,18.677 ; R11.1@24.092,16.637 24.1,16.645 R13.2@24.1,18.169 R13.2@24.257,18.012 ; R13.2@24.138,18.639 24.39,18.639 27.458,21.707 U1.8@27.458,23.093
NetC17_1: C17.1 R6.1 R14.2 U1.2 | length 7.4
  Bottom Layer w0.4: R6.1@34.374,21.331 34.374,19.909 C17.1@34.425,19.858 R14.2@35.949,19.858
  Bottom Layer w0.45: U1.2@31.358,23.093 31.358,22.252 31.377,22.233 31.377,22.073 32.106,21.344 32.948,21.344 32.961,21.331 R6.1@34.374,21.331
NetC18_1: C18.1 U1.7 | length 3.6
  Bottom Layer w0.45: C18.1@27.186,19.858 27.186,20.201 28.108,21.123 U1.7@28.108,23.093
NetC19_1: C19.1 U1.5 | length 3.5
  Bottom Layer w0.45: U1.5@29.408,23.093 29.408,20.557 C19.1@30.107,19.858
NetD1_1: D1.1 D1.3 L1.2 Q2.4 TP3.1
  other v2: 21.082,42.037 23.368,42.037 25.654,42.037 21.082,44.45 23.368,44.45 25.654,44.45 21.082,46.863 23.368,46.863 25.654,46.863
  other v3: 17.526,50.038 22.606,50.038 27.686,50.038 20.066,52.578 17.526,55.118 27.686,55.118 20.066,57.658 22.606,60.198 27.686,60.198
